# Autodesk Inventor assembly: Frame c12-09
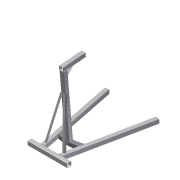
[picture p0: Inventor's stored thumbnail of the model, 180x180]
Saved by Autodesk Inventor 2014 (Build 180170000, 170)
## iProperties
Created: 2011-01
Part Number: Frame c12-09
Document SubType Name: Assembly
Designer: Thom Tremblay
_FrameDoc: Frame Assembly
_Version: 15.0.0
Author: Thom Tremblay
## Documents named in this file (20)
- C:\Inventor 2014 Essentials\Assemblies\Chapter 12\Frame\Frame c12-09.iam
- C:\Inventor 2014 Essentials\Assemblies\Chapter 12\Frame\Skeleton-c12-09.ipt
- C:\Inventor 2014 Essentials\Assemblies\Chapter 12\Frame\ANSI 3x3x3_16 00000043.ipt
- ANSI 3x3x3_16 00000043.ipt
- C:\Inventor 2014 Essentials\Assemblies\Chapter 12\Frame\ANSI 3x3x3_16 00000044.ipt
- ANSI 3x3x3_16 00000044.ipt
- C:\Inventor 2014 Essentials\Assemblies\Chapter 12\Frame\ANSI 3x3x3_16 00000045.ipt
- ANSI 3x3x3_16 00000045.ipt
- C:\Inventor 2014 Essentials\Assemblies\Chapter 12\Frame\ANSI 3x3x3_16 00000047.ipt
- ANSI 3x3x3_16 00000047.ipt
- C:\Inventor 2014 Essentials\Assemblies\Chapter 12\Frame\ANSI 3x3x3_16 00000048.ipt
- ANSI 3x3x3_16 00000048.ipt
- C:\Inventor 2014 Essentials\Assemblies\Chapter 12\Frame\ANSI 2 1_4x3_16 00000049.ipt
- ANSI 2 1_4x3_16 00000049.ipt
- C:\Inventor 2014 Essentials\Assemblies\Chapter 12\Frame\ANSI L 1.5 x 1.5 x 3_16 00000050.ipt
- ANSI L 1.5 x 1.5 x 3_16 00000050.ipt
- C:\Inventor 2014 Essentials\Assemblies\Chapter 12\Frame\ANSI L 1.5 x 1.5 x 3_16 00000051.ipt
- ANSI L 1.5 x 1.5 x 3_16 00000051.ipt
- C:\Inventor 2014 Essentials\Assemblies\Chapter 12\Frame\ANSI 3x3x3_16 00000062.ipt
- ANSI 3x3x3_16 00000062.ipt
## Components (10 placed, 10 different names)
1. Frame Reference Model
2. ANSI 3x3x3_16 00000043:1
3. ANSI 3x3x3_16 00000044:1
4. ANSI 3x3x3_16 00000045:1
5. ANSI 3x3x3_16 00000047:1
6. ANSI 3x3x3_16 00000048:1
7. ANSI 2 1_4x3_16 00000049:1
8. ANSI L 1.5 x 1.5 x 3_16 00000050:1
9. ANSI L 1.5 x 1.5 x 3_16 00000051:1
10. ANSI 3x3x3_16 00000062:1
